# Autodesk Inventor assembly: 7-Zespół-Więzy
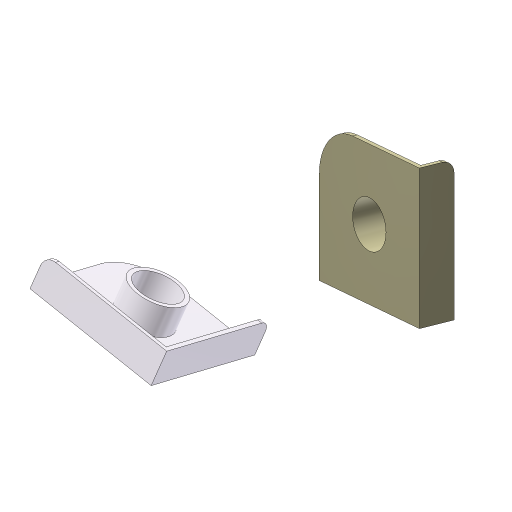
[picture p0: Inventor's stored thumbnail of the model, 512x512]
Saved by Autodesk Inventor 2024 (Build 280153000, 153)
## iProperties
Company: ATC
Shininess: 20.0
Length Units: 11269
Angle Units: 11279
Time Units: 11290
Mass Units: 11283
Length Display Precision: 3
Angle Display Precision: 2
Compacted: True
Created: 2023-03
Part Number: 7-Zespół-Więzy
Document SubType Name: Assembly
Designer: Andrzej Jaskulski
Checked By: A.J.
Engr Approved By: Andrzej Jaskulski
Mfg Approved By: Andrzej Jaskulski
Authority: A.J.
Density: 0.0
Volumn: 0.0
Area: 0.0
PropertySet Name: Model Information
Control State: 0
Master: False
Checked Out: False
Title: A.J.: Kurs R2024-MEP
Author: Andrzej Jaskulski
Revision Number: 1/24
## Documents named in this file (2)
- C:\Users\AndJas\Documents\R2024-MEP\Obszar roboczy\7-Zespół-Więzy.iam
- C:\Users\AndJas\Documents\R2024-MEP\Obszar roboczy\ss.ipt
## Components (2 placed, 1 different names)
1. ss:1
2. ss:2
